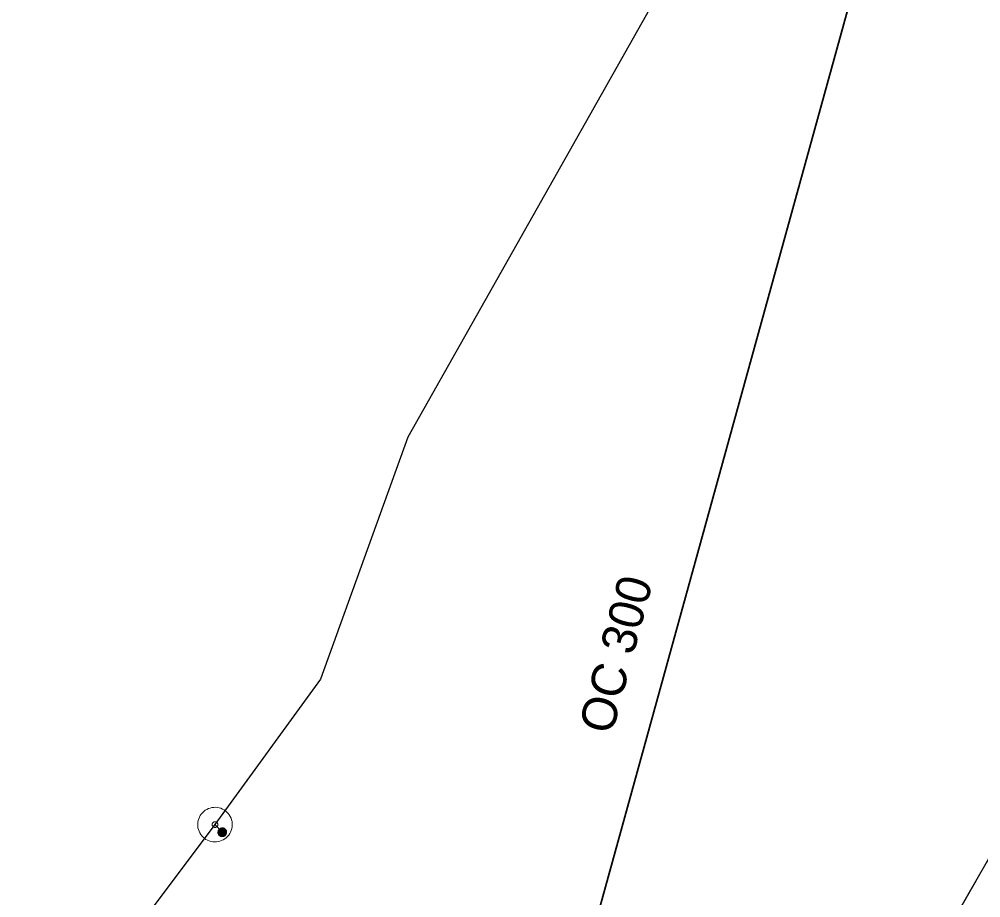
# Model space of a CAD drawing. Extents: x -724358 to -723714, y -973310 to -972026.
# Drawn here: x -724124.29 to -724096.49, y -972992.46 to -972967.06 of the extents above; entities that cross this region are included whole.
import ezdxf

# ---------------------------------------------------------------- set-up
doc = ezdxf.new("R2010")
doc.units = 0
doc.header["$LTSCALE"] = 0.4
doc.linetypes.add('MEDIUM_DASHED', pattern=[4.5, 3, -1.5])
for name, color, linetype, lineweight in [('1', 7, 'Continuous', 13), ('14', 7, 'Continuous', 13), ('17', 7, 'Continuous', 25), ('47', 7, 'Continuous', 13), ('9', 7, 'Continuous', 13)]:
    doc.layers.add(name, color=color, linetype=linetype, lineweight=lineweight)

msp = doc.modelspace()

# ---------------------------------------------------------------- linework, layer by layer
at = {"layer": '1', "linetype": 'MEDIUM_DASHED', "lineweight": 25}
msp.add_lwpolyline([(-723809.944, -972026.35), (-723713.647, -972034.723), (-723734.581, -972361.295), (-724123.956, -973039.561), (-724241.187, -973309.611), (-724358.418, -973148.418), (-723860.186, -972315.24)], close=True, dxfattribs=at)
at = {"layer": '1', "lineweight": 25}
msp.add_lwpolyline([(-724019.563, -972857.716), (-724123.956, -973039.561)], dxfattribs=at)
at = {"layer": '14'}
msp.add_line((-724118.629, -972990.349), (-724118.419, -972990.569), dxfattribs=at)
at = {"layer": '17'}
for points in [[(-724073.199, -972908.18), (-724086.44, -972931.51), (-724095.37, -972947.8), (-724113.059, -972979.149), (-724115.579, -972986.14), (-724118.629, -972990.349)], [(-724118.629, -972990.349), (-724131.039, -973006.89), (-724136.75, -973016.03), (-724154.829, -973009.05)]]:
    msp.add_lwpolyline(points, dxfattribs=at)
at = {"layer": '17', "lineweight": 35}
msp.add_lwpolyline([(-724113.111, -973013.057), (-724097.71, -972957.24), (-724070.768, -972909.289)], dxfattribs=at)
at = {"layer": '47'}
for points in [[(-724118.133, -972990.415), (-724118.129, -972990.363), (-724118.13, -972990.31), (-724118.137, -972990.259), (-724118.149, -972990.208), (-724118.166, -972990.158), (-724118.189, -972990.11), (-724118.217, -972990.066), (-724118.248, -972990.025), (-724118.284, -972989.987), (-724118.323, -972989.952), (-724118.367, -972989.922), (-724118.413, -972989.898), (-724118.461, -972989.878), (-724118.511, -972989.863), (-724118.562, -972989.853), (-724118.614, -972989.849), (-724118.667, -972989.85), (-724118.719, -972989.857), (-724118.769, -972989.869), (-724118.819, -972989.886), (-724118.867, -972989.909), (-724118.912, -972989.936), (-724118.953, -972989.968), (-724118.991, -972990.004), (-724119.025, -972990.043), (-724119.055, -972990.087), (-724119.08, -972990.133), (-724119.099, -972990.181), (-724119.114, -972990.231), (-724119.124, -972990.282), (-724119.128, -972990.334), (-724119.127, -972990.387), (-724119.121, -972990.439), (-724119.108, -972990.489), (-724119.091, -972990.539), (-724119.069, -972990.586), (-724119.042, -972990.631), (-724119.01, -972990.673), (-724118.973, -972990.711), (-724118.934, -972990.745), (-724118.89, -972990.775), (-724118.845, -972990.8), (-724118.796, -972990.819), (-724118.746, -972990.834), (-724118.695, -972990.844), (-724118.643, -972990.848), (-724118.59, -972990.847), (-724118.539, -972990.841), (-724118.488, -972990.828), (-724118.438, -972990.811), (-724118.391, -972990.789), (-724118.347, -972990.761), (-724118.305, -972990.73), (-724118.267, -972990.693), (-724118.232, -972990.654), (-724118.202, -972990.61), (-724118.178, -972990.565), (-724118.158, -972990.516), (-724118.143, -972990.466)], [(-724118.547, -972990.359), (-724118.546, -972990.35), (-724118.547, -972990.342), (-724118.548, -972990.334), (-724118.55, -972990.326), (-724118.553, -972990.317), (-724118.557, -972990.31), (-724118.561, -972990.302), (-724118.566, -972990.295), (-724118.572, -972990.289), (-724118.578, -972990.284), (-724118.586, -972990.279), (-724118.593, -972990.274), (-724118.601, -972990.271), (-724118.609, -972990.268), (-724118.618, -972990.267), (-724118.627, -972990.266), (-724118.635, -972990.267), (-724118.643, -972990.268), (-724118.651, -972990.27), (-724118.66, -972990.273), (-724118.667, -972990.277), (-724118.675, -972990.281), (-724118.682, -972990.286), (-724118.689, -972990.292), (-724118.693, -972990.298), (-724118.698, -972990.306), (-724118.703, -972990.313), (-724118.706, -972990.321), (-724118.709, -972990.329), (-724118.71, -972990.338), (-724118.711, -972990.347), (-724118.71, -972990.355), (-724118.709, -972990.363), (-724118.707, -972990.371), (-724118.704, -972990.38), (-724118.701, -972990.387), (-724118.696, -972990.395), (-724118.691, -972990.402), (-724118.685, -972990.409), (-724118.679, -972990.413), (-724118.671, -972990.418), (-724118.664, -972990.423), (-724118.656, -972990.426), (-724118.648, -972990.429), (-724118.639, -972990.43), (-724118.63, -972990.431), (-724118.622, -972990.43), (-724118.614, -972990.429), (-724118.606, -972990.427), (-724118.597, -972990.424), (-724118.59, -972990.421), (-724118.582, -972990.416), (-724118.575, -972990.411), (-724118.569, -972990.405), (-724118.564, -972990.399), (-724118.559, -972990.391), (-724118.554, -972990.384), (-724118.551, -972990.376), (-724118.548, -972990.368)]]:
    msp.add_lwpolyline(points, close=True, dxfattribs=at)
at = {"layer": '9'}
for points in [[(-724118.545, -972990.569), (-724118.545, -972990.582), (-724118.543, -972990.595), (-724118.54, -972990.608), (-724118.535, -972990.62), (-724118.529, -972990.632), (-724118.522, -972990.643), (-724118.514, -972990.653), (-724118.504, -972990.663), (-724118.494, -972990.671), (-724118.483, -972990.678), (-724118.471, -972990.684), (-724118.459, -972990.689), (-724118.446, -972990.692), (-724118.433, -972990.694), (-724118.42, -972990.696), (-724118.407, -972990.695), (-724118.394, -972990.693), (-724118.381, -972990.69), (-724118.369, -972990.685), (-724118.357, -972990.679), (-724118.346, -972990.672), (-724118.336, -972990.664), (-724118.326, -972990.654), (-724118.318, -972990.644), (-724118.311, -972990.633), (-724118.305, -972990.621), (-724118.3, -972990.609), (-724118.297, -972990.596), (-724118.295, -972990.583), (-724118.293, -972990.57), (-724118.294, -972990.557), (-724118.296, -972990.544), (-724118.299, -972990.531), (-724118.304, -972990.519), (-724118.309, -972990.507), (-724118.317, -972990.496), (-724118.325, -972990.486), (-724118.335, -972990.476), (-724118.345, -972990.468), (-724118.356, -972990.461), (-724118.368, -972990.455), (-724118.38, -972990.45), (-724118.393, -972990.447), (-724118.406, -972990.445), (-724118.419, -972990.444), (-724118.432, -972990.444), (-724118.445, -972990.446), (-724118.458, -972990.449), (-724118.47, -972990.454), (-724118.482, -972990.46), (-724118.493, -972990.467), (-724118.503, -972990.475), (-724118.513, -972990.485), (-724118.521, -972990.495), (-724118.528, -972990.506), (-724118.534, -972990.518), (-724118.539, -972990.53), (-724118.542, -972990.543), (-724118.544, -972990.556)], [(-724118.525, -972990.569), (-724118.526, -972990.58), (-724118.524, -972990.591), (-724118.521, -972990.602), (-724118.517, -972990.612), (-724118.512, -972990.622), (-724118.506, -972990.631), (-724118.499, -972990.64), (-724118.491, -972990.648), (-724118.482, -972990.655), (-724118.473, -972990.661), (-724118.463, -972990.666), (-724118.453, -972990.67), (-724118.442, -972990.673), (-724118.431, -972990.676), (-724118.42, -972990.676), (-724118.409, -972990.676), (-724118.398, -972990.674), (-724118.387, -972990.671), (-724118.377, -972990.667), (-724118.367, -972990.662), (-724118.358, -972990.656), (-724118.349, -972990.649), (-724118.341, -972990.641), (-724118.334, -972990.632), (-724118.328, -972990.623), (-724118.323, -972990.613), (-724118.319, -972990.603), (-724118.316, -972990.592), (-724118.314, -972990.581), (-724118.313, -972990.57), (-724118.313, -972990.559), (-724118.315, -972990.548), (-724118.318, -972990.537), (-724118.322, -972990.527), (-724118.327, -972990.517), (-724118.333, -972990.508), (-724118.34, -972990.499), (-724118.348, -972990.491), (-724118.357, -972990.484), (-724118.366, -972990.478), (-724118.376, -972990.473), (-724118.386, -972990.469), (-724118.397, -972990.466), (-724118.407, -972990.464), (-724118.419, -972990.464), (-724118.43, -972990.463), (-724118.441, -972990.465), (-724118.452, -972990.468), (-724118.462, -972990.472), (-724118.472, -972990.477), (-724118.481, -972990.483), (-724118.49, -972990.49), (-724118.498, -972990.498), (-724118.505, -972990.507), (-724118.511, -972990.516), (-724118.516, -972990.526), (-724118.52, -972990.536), (-724118.523, -972990.547), (-724118.525, -972990.558)], [(-724118.506, -972990.569), (-724118.506, -972990.578), (-724118.505, -972990.587), (-724118.502, -972990.596), (-724118.499, -972990.604), (-724118.495, -972990.612), (-724118.49, -972990.62), (-724118.483, -972990.627), (-724118.478, -972990.633), (-724118.471, -972990.639), (-724118.463, -972990.644), (-724118.455, -972990.648), (-724118.447, -972990.651), (-724118.438, -972990.654), (-724118.429, -972990.655), (-724118.42, -972990.657), (-724118.411, -972990.656), (-724118.402, -972990.655), (-724118.393, -972990.652), (-724118.385, -972990.649), (-724118.377, -972990.645), (-724118.369, -972990.64), (-724118.362, -972990.634), (-724118.356, -972990.628), (-724118.35, -972990.621), (-724118.345, -972990.613), (-724118.341, -972990.605), (-724118.338, -972990.597), (-724118.335, -972990.588), (-724118.334, -972990.579), (-724118.331, -972990.57), (-724118.333, -972990.561), (-724118.334, -972990.552), (-724118.337, -972990.543), (-724118.34, -972990.535), (-724118.344, -972990.527), (-724118.349, -972990.519), (-724118.355, -972990.512), (-724118.361, -972990.506), (-724118.368, -972990.5), (-724118.376, -972990.495), (-724118.384, -972990.491), (-724118.392, -972990.488), (-724118.401, -972990.485), (-724118.41, -972990.484), (-724118.419, -972990.483), (-724118.428, -972990.483), (-724118.437, -972990.484), (-724118.446, -972990.487), (-724118.454, -972990.49), (-724118.462, -972990.494), (-724118.47, -972990.499), (-724118.477, -972990.505), (-724118.483, -972990.511), (-724118.489, -972990.518), (-724118.494, -972990.526), (-724118.498, -972990.534), (-724118.501, -972990.542), (-724118.504, -972990.551), (-724118.505, -972990.56)], [(-724118.486, -972990.569), (-724118.486, -972990.576), (-724118.485, -972990.583), (-724118.483, -972990.59), (-724118.481, -972990.596), (-724118.478, -972990.602), (-724118.474, -972990.608), (-724118.47, -972990.614), (-724118.465, -972990.619), (-724118.459, -972990.623), (-724118.453, -972990.627), (-724118.447, -972990.63), (-724118.441, -972990.633), (-724118.434, -972990.634), (-724118.427, -972990.637), (-724118.42, -972990.637), (-724118.413, -972990.637), (-724118.406, -972990.635), (-724118.399, -972990.634), (-724118.393, -972990.631), (-724118.386, -972990.628), (-724118.381, -972990.624), (-724118.375, -972990.62), (-724118.37, -972990.615), (-724118.366, -972990.609), (-724118.362, -972990.603), (-724118.358, -972990.597), (-724118.356, -972990.591), (-724118.354, -972990.584), (-724118.353, -972990.577), (-724118.352, -972990.57), (-724118.352, -972990.563), (-724118.353, -972990.556), (-724118.355, -972990.549), (-724118.358, -972990.543), (-724118.361, -972990.536), (-724118.365, -972990.531), (-724118.369, -972990.525), (-724118.374, -972990.52), (-724118.38, -972990.516), (-724118.385, -972990.512), (-724118.392, -972990.509), (-724118.398, -972990.506), (-724118.405, -972990.504), (-724118.412, -972990.503), (-724118.419, -972990.503), (-724118.426, -972990.503), (-724118.433, -972990.503), (-724118.44, -972990.505), (-724118.446, -972990.508), (-724118.452, -972990.511), (-724118.458, -972990.515), (-724118.464, -972990.519), (-724118.469, -972990.524), (-724118.473, -972990.53), (-724118.477, -972990.535), (-724118.48, -972990.542), (-724118.483, -972990.548), (-724118.483, -972990.555), (-724118.486, -972990.562)], [(-724118.466, -972990.569), (-724118.466, -972990.574), (-724118.466, -972990.579), (-724118.465, -972990.584), (-724118.463, -972990.588), (-724118.461, -972990.593), (-724118.458, -972990.597), (-724118.455, -972990.6), (-724118.451, -972990.604), (-724118.448, -972990.607), (-724118.444, -972990.61), (-724118.439, -972990.612), (-724118.434, -972990.614), (-724118.43, -972990.615), (-724118.425, -972990.617), (-724118.42, -972990.617), (-724118.415, -972990.617), (-724118.41, -972990.616), (-724118.405, -972990.615), (-724118.401, -972990.613), (-724118.396, -972990.611), (-724118.392, -972990.608), (-724118.388, -972990.605), (-724118.385, -972990.601), (-724118.382, -972990.598), (-724118.379, -972990.594), (-724118.377, -972990.589), (-724118.375, -972990.585), (-724118.374, -972990.58), (-724118.373, -972990.575), (-724118.372, -972990.57), (-724118.372, -972990.565), (-724118.373, -972990.56), (-724118.374, -972990.555), (-724118.376, -972990.551), (-724118.378, -972990.546), (-724118.381, -972990.542), (-724118.384, -972990.538), (-724118.387, -972990.535), (-724118.391, -972990.532), (-724118.395, -972990.529), (-724118.4, -972990.527), (-724118.404, -972990.525), (-724118.409, -972990.524), (-724118.414, -972990.523), (-724118.419, -972990.523), (-724118.424, -972990.523), (-724118.429, -972990.524), (-724118.434, -972990.524), (-724118.438, -972990.526), (-724118.443, -972990.528), (-724118.447, -972990.531), (-724118.45, -972990.534), (-724118.454, -972990.537), (-724118.456, -972990.541), (-724118.46, -972990.545), (-724118.462, -972990.55), (-724118.464, -972990.554), (-724118.465, -972990.559), (-724118.466, -972990.564)], [(-724118.446, -972990.569), (-724118.446, -972990.572), (-724118.447, -972990.575), (-724118.446, -972990.577), (-724118.445, -972990.58), (-724118.444, -972990.583), (-724118.442, -972990.585), (-724118.44, -972990.587), (-724118.438, -972990.589), (-724118.436, -972990.591), (-724118.434, -972990.593), (-724118.431, -972990.595), (-724118.428, -972990.596), (-724118.426, -972990.596), (-724118.423, -972990.597), (-724118.42, -972990.597), (-724118.417, -972990.597), (-724118.414, -972990.597), (-724118.411, -972990.596), (-724118.409, -972990.595), (-724118.406, -972990.594), (-724118.404, -972990.592), (-724118.401, -972990.59), (-724118.399, -972990.588), (-724118.398, -972990.586), (-724118.396, -972990.584), (-724118.395, -972990.581), (-724118.393, -972990.578), (-724118.393, -972990.576), (-724118.392, -972990.573), (-724118.391, -972990.57), (-724118.392, -972990.567), (-724118.392, -972990.564), (-724118.393, -972990.561), (-724118.394, -972990.559), (-724118.395, -972990.556), (-724118.397, -972990.554), (-724118.398, -972990.551), (-724118.4, -972990.549), (-724118.403, -972990.548), (-724118.405, -972990.546), (-724118.407, -972990.545), (-724118.41, -972990.544), (-724118.413, -972990.543), (-724118.416, -972990.543), (-724118.419, -972990.542), (-724118.422, -972990.543), (-724118.425, -972990.542), (-724118.427, -972990.544), (-724118.43, -972990.544), (-724118.433, -972990.545), (-724118.434, -972990.547), (-724118.437, -972990.548), (-724118.439, -972990.55), (-724118.441, -972990.553), (-724118.443, -972990.555), (-724118.444, -972990.558), (-724118.445, -972990.56), (-724118.446, -972990.563), (-724118.446, -972990.566)], [(-724118.427, -972990.569), (-724118.427, -972990.571), (-724118.427, -972990.571), (-724118.426, -972990.571), (-724118.426, -972990.573), (-724118.427, -972990.574), (-724118.425, -972990.574), (-724118.425, -972990.574), (-724118.425, -972990.576), (-724118.425, -972990.576), (-724118.424, -972990.577), (-724118.422, -972990.577), (-724118.422, -972990.577), (-724118.422, -972990.578), (-724118.42, -972990.578), (-724118.42, -972990.578), (-724118.419, -972990.578), (-724118.418, -972990.578), (-724118.418, -972990.577), (-724118.417, -972990.577), (-724118.415, -972990.577), (-724118.415, -972990.576), (-724118.415, -972990.576), (-724118.414, -972990.575), (-724118.414, -972990.575), (-724118.412, -972990.574), (-724118.412, -972990.573), (-724118.411, -972990.572), (-724118.411, -972990.572), (-724118.411, -972990.571), (-724118.411, -972990.57), (-724118.411, -972990.569), (-724118.411, -972990.568), (-724118.411, -972990.568), (-724118.412, -972990.567), (-724118.412, -972990.566), (-724118.413, -972990.565), (-724118.413, -972990.565), (-724118.414, -972990.564), (-724118.414, -972990.564), (-724118.415, -972990.563), (-724118.416, -972990.563), (-724118.417, -972990.562), (-724118.417, -972990.562), (-724118.418, -972990.562), (-724118.419, -972990.562), (-724118.42, -972990.562), (-724118.421, -972990.562), (-724118.421, -972990.562), (-724118.422, -972990.563), (-724118.423, -972990.562), (-724118.424, -972990.564), (-724118.424, -972990.564), (-724118.425, -972990.564), (-724118.425, -972990.564), (-724118.426, -972990.566), (-724118.426, -972990.567), (-724118.426, -972990.568), (-724118.427, -972990.568), (-724118.427, -972990.569)]]:
    msp.add_lwpolyline(points, close=True, dxfattribs=at)

# ---------------------------------------------------------------- texts
at = {"layer": '1'}
msp.add_text('OC 300', height=1, rotation=75, dxfattribs=at).set_placement((-724107.157, -972987.777))

doc.saveas('drawing.dxf')
